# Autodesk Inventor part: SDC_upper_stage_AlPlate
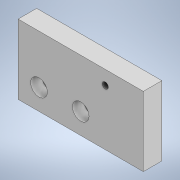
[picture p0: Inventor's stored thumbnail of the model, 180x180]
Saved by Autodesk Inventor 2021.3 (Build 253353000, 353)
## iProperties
Created: 2022-01
Part Number: SDC_upper_stage_AlPlate
Material: 一般
Document SubType Name: Modeling
Designer: kengo
Density: 1 g/cm^3
Appearance: 既定
Author: kengo
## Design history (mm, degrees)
sketch "スケッチ1"
  geometry: L1 (-78.387, 47.152)-(56.613, 47.152); L2 (56.613, 47.152)-(56.613, -27.848); L3 (56.613, -27.848)-(-78.387, -27.848); L4 (-78.387, -27.848)-(-78.387, 47.152); 1 further point
  constraints: 8 end point, 2 parallel, 1 horizontal, 1 perpendicular
  dimensions: "d0" = 135 distance of L1.start L1.end; "d1" = 75 distance of L3.end L1.start
extrude "押し出し1" new body sketch "スケッチ1" distance "d2" = 20; taper "d3" = 0 deg
sketch "スケッチ2"
  geometry: L1 (-78.387, 47.152)-(-78.387, -27.848) reference; L2 (-78.387, -27.848)-(56.613, -27.848) reference; 3 further points
  dimensions: "d4" = 45 distance of point (-10.887, -5.348) point (-55.887, -5.348); "d5" = 22.5 distance from line of L1 point (-55.887, -5.348); "d6" = 22.5 distance from line of L2 point (-55.887, -5.348); "d7" = 22.5 distance from line of L2 point (-10.887, -5.348)
hole "穴1" sketch "スケッチ2" at (-55.887, -5.348), (-10.887, -5.348) diameter "d8" = 12; stored, may be unused: countersink angle "d12" = 90 deg, drill point angle "d14" = 118 deg; dims "d9" = 16, "d10" = 18, "d11" = 12, "d13" = 22.2
sketch "スケッチ4"
  geometry: L1 (56.613, -27.848)-(56.613, 47.152) reference; L2 (-78.387, -27.848)-(56.613, -27.848) reference; 2 further points
  dimensions: "d26" = 41 distance from line of L1 point (15.613, 32.152); "d27" = 60 distance from line of L2 point (15.613, 32.152)
hole "穴3" sketch "スケッチ4" at (15.613, 32.152) diameter "d28" = 6.647; stored, may be unused: countersink angle "d32" = 90 deg, drill point angle "d34" = 118 deg; dims "d29" = 16, "d30" = 14, "d31" = 8, "d33" = 21.1
node "ソリッド1"
